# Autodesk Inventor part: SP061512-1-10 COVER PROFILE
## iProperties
Created: 2012-06
Part Number: SP061512-1-10 COVER PROFILE
Material: PVC-U
Document SubType Name: Modeling
Designer: Administrator
Density: 1.4 g/cm^3
Mass: 64.4432 g
Surface Area: 886.766 cm^2
Volume: 46.0309 cm^3
Author: Administrator
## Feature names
1. Extrusion3
